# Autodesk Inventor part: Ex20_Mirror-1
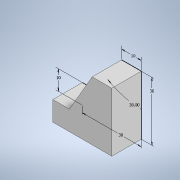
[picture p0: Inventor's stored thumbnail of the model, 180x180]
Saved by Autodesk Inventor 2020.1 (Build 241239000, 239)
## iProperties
Created: 2019-11
Part Number: Ex20_Mirror-1
Material: Generic
Document SubType Name: Modeling
Designer: Synergysoft Dell02
Density: 1 g/cm^3
Appearance: Default
Author: Synergysoft Dell02
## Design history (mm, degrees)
sketch "Sketch1"
  geometry: L1 (0, 30)-(-10, 30); L2 (-10, 30)-(-21.547, 10); L3 (-21.547, 10)-(-30, 10); L4 (-30, 10)-(-30, 0); L5 (-30, 0)-(0, 0); L6 (0, 0)-(0, 30)
  constraints: 12 end point, 3 perpendicular, 1 horizontal, 1 parallel
  dimensions: "d0" = 10 distance between parallel lines of L5 L3; "d1" = 30 deg angle of L6 L2; "d2" = 30 distance of L5.end L1.start; "d3" = 30 distance between parallel lines of L6 L4; "d4" = 10 distance of L1.start L1.end
extrude "Extrusion1" new body sketch "Sketch1" distance "d5" = 15; taper "d6" = 0 deg
body "Solid1"
